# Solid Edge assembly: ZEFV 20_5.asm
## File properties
Title: Zylinder
Author: bmolnar
Template: iso metric assembly.asm
Last saved by: bmolnar
Revision: 9
Application: Solid Edge
Username: bmolnar
Dokumentum tartalom típus: 1
Document Number: ZEFV 20/5
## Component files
Mutter.par
Profilrohr.par
Kolbenstange.par
Kit_2.par
Kit_1.par
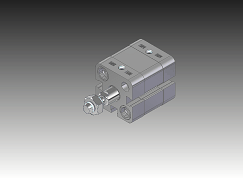
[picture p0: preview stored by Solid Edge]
